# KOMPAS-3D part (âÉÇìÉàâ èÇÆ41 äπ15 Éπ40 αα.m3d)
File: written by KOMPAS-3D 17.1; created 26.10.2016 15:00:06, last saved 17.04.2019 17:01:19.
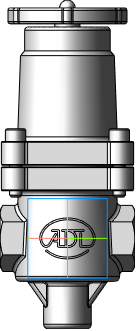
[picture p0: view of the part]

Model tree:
1. Операция без истории:3  (labels: Сталь 20  ГОСТ 1050-88)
